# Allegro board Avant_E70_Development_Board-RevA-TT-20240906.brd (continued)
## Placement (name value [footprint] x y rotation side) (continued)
R697  2k  [R0603]  139.57 64.56 180 top
R698  732  [R0603]  139.57 63.29 180 top
R702  10K  [R0402]  137.54 73.45 270 bottom
R703  10K-DNI  [R0402]  137.92 71.29 90 bottom
R704  0-DNI  [R0402]  136.4 73.45 90 bottom
R705  10K  [R0402]  138.56 73.45 270 top
R706  10K-DNI  [R0402]  140.84 73.45 270 top
R707  10K-DNI  [R0402]  141.86 73.45 270 top
R708  10K-DNI  [R0603]  139.57 73.45 0 bottom
R709  240-DNI  [R0402]  80.77 71.17 90 bottom
R710  240-DNI  [R0402]  88.26 61.77 0 bottom
R711  240-DNI  [R0402]  62.48 66.72 270 bottom
R712  240-DNI  [R0402]  62.48 72.69 90 bottom
R713  240-DNI  [R0402]  62.48 68.88 90 bottom
R714  0.01-DNI  [R0603]  80.77 91.36 90 bottom
R715  0-DNI  [R0402]  101.98 102.79 0 bottom
R716  0-DNI  [R0402]  154.31 93.14 270 top
RDAT  VTTVREF  [TP_50]  156.24 84.95 0 top
SB_3V30  T POINT R  [TP]  132.46 49.96 0 top
ST  VTTVREF  [TP_50]  72.9 58.34 0 top
SW1  -  [430182043816]  50.04 131.62 90 top
SW2  -  [430182043816]  42.93 131.62 90 top
SW3  TDA DIP-8  [TDA08H0SB1]  55.76 46.53 270 top
SW4  -  [430182043816]  57.02 131.62 90 top
SW5  -  [430182043816]  64.01 131.62 90 top
SW7  SW-Wurth_452403012014  [452403012014]  37.72 109.9 270 top
SW8  -  [430182043816]  137.16 57.32 180 top
TP25  TestPoint_SMT  [TPC32]  154.05 12.87 0 top
TP26  TestPoint_SMT  [TPC32]  154.05 19.73 0 top
TP_AF15  T POINT R  [TP]  13.12 36.18 180 top
TP_AF16  T POINT R  [TP]  13.12 33.64 180 top
TP_AG14  T POINT R  [TP]  8.04 31.1 180 top
TP_AG15  T POINT R  [TP]  15.66 36.18 180 top
TP_AH14  T POINT R  [TP]  10.58 31.1 180 top
TP_AH15  T POINT R  [TP]  15.66 33.64 180 top
TP_AJ16  T POINT R  [TP]  2.96 31.1 180 top
TP_AK12  T POINT R  [TP]  5.5 36.18 180 top
TP_AK13  T POINT R  [TP]  5.5 33.64 180 top
TP_AK14  T POINT R  [TP]  15.66 31.1 180 top
TP_AK15  T POINT R  [TP]  13.12 31.1 180 top
TP_AK16  T POINT R  [TP]  5.5 31.1 180 top
TP_AL13  T POINT R  [TP]  8.04 36.18 180 top
TP_AM13  T POINT R  [TP]  8.04 33.64 180 top
TP_AN12  T POINT R  [TP]  8.04 38.72 180 top
TP_AN13  T POINT R  [TP]  13.12 38.72 180 top
TP_AP10  T POINT R  [TP]  2.96 38.72 180 top
TP_AP11  T POINT R  [TP]  5.5 38.72 180 top
TP_AP12  T POINT R  [TP]  10.58 38.72 180 top
TP_AP13  T POINT R  [TP]  15.66 38.72 180 top
TP_FMC2_VREFB  TestPoint  [TP50]  42.04 14.78 0 top
TP_M2C_B_1_1  TestPoint  [TP50]  5.5 42.21 0 top
TP_M2C_B_1_2  TestPoint  [TP50]  2.96 42.21 0 top
TP_M2C_B_2_1  TestPoint  [TP50]  116.84 7.16 0 top
TP_M2C_B_2_2  TestPoint  [TP50]  116.84 9.7 0 top
TP_R7  T POINT R  [TP]  30.86 110.92 0 top
U1  FT2232HL  [TQFP64_0P5_12P2X12P2_H1P6]  24.31 131.64 0 top
U2  93LC56C-I/SN  [SO8_50_244]  23.97 131.31 270 bottom
U3  LAV-AT-E70-LFG1156  [LAV-AT-500-L_1156]  80.9 79.93 0 top
U4  W25Q512JVEIM  [8-WSON]  53.47 122.35 0 top
U5  MT53E512M32D1ZW-046 WT:B  [BGA_SDRAM_200]  114.55 80.44 90 top
U6  BD9D321EFJ  [HTSOP_8_BD9D321]  40.67 48.26 180 top
U17  AP62201WU-7  [TSOT26_AP62201WU-7]  148.93 134.97 0 top
U32  BD9D321EFJ  [HTSOP_8_BD9D321]  32.41 24.66 270 top
U34  AP62201WU-7  [TSOT26_AP62201WU-7]  134.94 83 0 top
U35  AP62201WU-7  [TSOT26_AP62201WU-7]  148.93 105.76 0 top
U36  AP62201WU-7  [TSOT26_AP62201WU-7]  148.49 92.55 0 top
U37  AP62201WU-7  [TSOT26_AP62201WU-7]  134.27 96.08 0 top
U38  AP62201WU-7  [TSOT26_AP62201WU-7]  134.27 124.81 0 top
U39  AP62201WU-7  [TSOT26_AP62201WU-7]  134.27 110.33 0 top
U40  AP62201WU-7  [TSOT26_AP62201WU-7]  148.93 120.49 0 top
U41  AP62201WU-7  [TSOT26_AP62201WU-7]  148.59 81.2 0 top
U43  RT7298AHGQW  [14-WQFN]  126.9 41.68 180 top
U44  NCP133  [XFDFN6]  102.49 106.55 0 top
U45  -  [LPTM21L-CAG100]  156.84 70.66 0 top
U46  PI4ULS3V204ZBEX  [TQFN-14]  109.85 36.75 90 bottom
U107  AP62201WU-7  [TSOT26_AP62201WU-7]  138.33 45.13 0 top
U107_EN  T POINT R  [TP]  142.38 47.09 0 top
U108  MPF52002GRE-0012-Z  [QFN24N4X4P0_5]  144.78 9.95 270 top
U109  ESD1L001W1T2G  [SC-88]  150.37 16.3 270 bottom
U110  MPQ4372GVTE-1001-AEC1-Z  [QFN-23]  123.19 23.67 90 top
U111  MPQ4372GVTE-1001-AEC1-Z  [QFN-23]  145.54 23.67 270 top
U114  TPS564242DRLR  [SOT-563-6]  27.43 37.51 270 top
U115  TPS564242DRLR  [SOT-563-6]  42.55 37.51 270 top
U116  RP115H181D-T1-FE  [SOT89-5]  96.77 125.4 180 top
U118  MP2013AGG  [QFN6-MP2013]  156.97 29.26 180 top
U119  MT53E512M32D1ZW-046 WT:B  [BGA_SDRAM_200]  114.55 66.72 90 top
U120  MPM3695GPJ-20-0022-T  [ECLGA-29-5X6X4R4]  139.06 68.5 270 top
UNK0V9  T POINT R  [TP]  5.5 20.94 180 top
UNK0V82  T POINT R  [TP]  8.04 23.48 180 top
UNK0V82_EN  T POINT R  [TP]  149.99 73.83 0 top
UNK1V  T POINT R  [TP]  8.04 26.02 180 top
UNK1V1  T POINT R  [TP]  10.58 20.94 180 top
UNK1V2  T POINT R  [TP]  15.66 20.94 180 top
UNK1V5  T POINT R  [TP]  13.12 26.02 180 top
UNK1V8  T POINT R  [TP]  15.66 23.48 180 top
UNK1V35  T POINT R  [TP]  13.12 20.94 180 top
UNK1V80_EN  T POINT R  [TP]  161.89 84.66 0 top
UNK2V5  T POINT R  [TP]  2.96 20.94 180 top
UNK3V3  T POINT R  [TP]  10.58 23.48 180 top
UNK5V  T POINT R  [TP]  13.12 23.48 180 top
UNK6T  VTTVREF  [TP_50]  72.9 55.8 0 top
UNK10T  VTTVREF  [TP_50]  72.9 53.26 0 top
UNK12V  T POINT R  [TP]  8.04 20.94 180 top
VCC_3V30_EN  T POINT R  [TP]  158.01 63.39 0 top
VCCAPLL4  TestPoint_SMT  [TPC32]  118.75 108 180 top
VCCAPLL7  TestPoint_SMT  [TPC32]  118.75 103.93 180 top
VCCAPLL10  TestPoint_SMT  [TPC32]  107.45 52.93 180 top
VCCAPLLW  TestPoint_SMT  [TPC32]  100.52 96.5 180 top
VCCAUX  TestPoint_SMT  [TPC32]  100.58 113.33 270 top
VCCIO0  TestPoint_SMT  [TPC32]  46.64 105.18 90 top
VCCIO1  TestPoint_SMT  [TPC32]  92.2 103.25 0 top
VCCIO2  TestPoint_SMT  [TPC32]  57.4 81.33 0 top
VCCIO3  TestPoint_SMT  [TPC32]  69.04 114.57 0 top
VCCIO4  TestPoint_SMT  [TPC32]  76.54 114.55 0 top
VCCIO5  TestPoint_SMT  [TPC32]  86.84 114.51 0 top
VCCIO6  TestPoint_SMT  [TPC32]  111 112.95 0 top
VCCIO7  TestPoint_SMT  [TPC32]  104.68 116.69 0 top
VCCIO8  TestPoint_SMT  [TPC32]  113.44 116.69 0 top
VCCIO9  TestPoint_SMT  [TPC32]  92.84 114.85 0 top
VCCIO10  TestPoint_SMT  [TPC32]  94.49 113.2 0 top
VCCIO11  TestPoint_SMT  [TPC32]  92.84 113.2 270 top
VCCIO12  TestPoint_SMT  [TPC32]  81.49 100.24 0 top
VCCIO13  TestPoint_SMT  [TPC32]  65.02 113.58 180 top
VCCIO14  TestPoint_SMT  [TPC32]  66.34 104.63 0 top
VCCORE  TestPoint_SMT  [TPC32]  109.47 89.84 180 top
VFMC1_3V30  VTTVREF  [TP_50]  32.7 57.26 90 top
VFMC1_ADJ  TestPoint_SMT  [TPC32]  26.67 34.84 270 top
VFMC2_3V30  VTTVREF  [TP_50]  22.61 17.7 180 top
VFMC2_ADJ  TestPoint_SMT  [TPC32]  41.78 34.84 270 top
WDAT  VTTVREF  [TP_50]  149.99 68.88 0 top
WRCLK  VTTVREF  [TP_50]  159.13 87.6 0 top
X1  7M-12.000MAAJ-T  [XTAL_4P_7M]  16.13 140 180 top
X3  ASDMB-125.000MHZ-XY-T  [X4-2520]  60.2 93.77 270 top
Y1  100 MHz  [SMD6_AX3HAF1]  101.94 90.53 180 top

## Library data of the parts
AP14 DONE INIT PB1-PB3 PROGRAMN PS_EN TP25 TP26 TP_FMC2_VREFB TP_M2C_B_1_1 TP_M2C_B_1_2 TP_M2C_B_2_1 TP_M2C_B_2_2 VCCAPLL4 VCCAPLL7 VCCAPLL10 VCCAPLLW VCCAUX VCCIO0-VCCIO14 VCCORE VFMC1_ADJ VFMC2_ADJ = T POINT R
ASC_CLK P_DONE P_INITN P_JTAGENB P_PROGN PTM_SCL PTM_SDA RDAT ST UNK6T UNK10T VFMC1_3V30 VFMC2_3V30 WDAT WRCLK = TP_SMD
C1-C5 C7 C8 C10-C13 C15-C18 C20-C22 C24-C27 C29-C32 C34 C38-C40 C42-C44 C46 C48 C54 C56-C58 C60 C61 C65 C66 C69 C94 C99 C100 C526 C527 C529-C533 C535-C542 C544-C546 C548 C561 C563 C564 C579 C580 C584 C587-C590 C592-C594 C596-C600 C625 C629 C721-C729 C1177-C1180 C1185-C1189 C1191 C1192 C1198 C1199 C1202 C1203 C1214 C1215 C1219 C1220 C1258 C1259 C1666 C1667 = 0u1_0402
C6 C9 = 4u7_0603
C14 C19 C33 C37 C41 C45 C47 C49-C53 C55 C59 C62-C64 C97 C98 C101 C103 C104 C207 C208 C528 C534 C543 C547 C556-C560 C562 C565 C586 C591 C595 C614-C619 C622-C624 C626 C628 C630 C1190 C1216-C1218 C1264-C1269 C1645 C1646 C1648-C1652 C1656-C1663 = 10uF_0603
C23 C138-C140 C163 C168 C169 C402 C403 C405 C620 C621 = CAP NP
C36 C396 C397 C466 C469 C471 C474 C483 C485 C488 C510 C512 C525 C631 C1221 C1223 C1225 C1227 C1255 C1257 = C-0402_10U_6.3V_X5R_TDK
C113 = CAP POL
C142-C152 C164-C167 C171-C174 C176-C178 C289-C292 C398-C401 C404 = CAP_1
C175 = CAP_SMT_0805
C287 C288 C293 C717 = C-0402_10nF_6.3V_X5R_MURATA
C385 C632 C634 C638 C645 C649 C653 C657 C658 C662 C674 C1181 = C_0.1uF_50V_CER_0402
C386 C387 C635 C636 C639 C640 C642 C643 C646 C647 C650 C651 C654 C655 C659 C660 C663 C664 C675 C676 C1183 C1184 = C-0603_22uF_10V_X5R_Samsung
C388 C641 C644 C648 C652 C656 C661 C665 C718 C719 = C_10uf_CER_25V_0603
C465 C467 C468 C470 C472 C473 C475-C482 C484 C486 C487 C489-C509 C511 C1222 C1224 C1226 C1228-C1254 C1256 C1665 = C-0201_0.1uF_100V_X5R_MURATA
C612 C613 = C-0402_22uF_X5R_6V3_Kyocera
C637 C1182 = C-0603_10uF_16V_X5R_TaiyoYuden
C672 = C-0402_180P
C673 = C-0402_8n2F_25V_X7R_MURATA
C677 = C-0402_10nF_16V_X7R_YAGEO
C713 C714 C1193-C1196 C1204-C1211 C1260 C1261 = C-0805_22uF_25V_X5R_Yageo
C720 C732 C733 = C-0402_0.1uF_10V_X5R_MURATA
C734 = C-0402_0.1uF_6.3V_X5R_MURATA_NP
C1647 C1653-C1655 C1668 = CAP_Electrolytic_SMD_OSCON_E7
D1 D5-D13 = LED-SMT1206_GREEN_3
D3 = ESDR0502
D4 = LED-SMT1206_RED_2
D22-D29 = D- RED_LED_0
D52 D77 = TMP_0
D60 = 7SEG_LDT-N2804RI _12-DIP
D61-D70 D73-D75 D78 = LED_GREEN_0
F1_3V3 F1_3V3AUX F1_ADJ F2_3V3 F2_3V3AUX F2_ADJ GND6-GND15 PLL0V82_EN SB_3V30 TP_AF15 TP_AF16 TP_AG14 TP_AG15 TP_AH14 TP_AH15 TP_AJ16 TP_AK12-TP_AK16 TP_AL13 TP_AM13 TP_AN12 TP_AN13 TP_AP10-TP_AP13 TP_R7 U107_EN UNK0V9 UNK0V82 UNK0V82_EN UNK1V UNK1V1 UNK1V2 UNK1V5 UNK1V8 UNK1V35 UNK1V80_EN UNK2V5 UNK3V3 UNK5V UNK12V VCC_3V30_EN = T POINT R_0
FB1-FB3 FB6 = INDUCTOR_1
FB4 FB24 = FB_0806_120R_TaiyoYuden
FB16 L1 L4 L5 L8 L10 L13-L18 L20 L23 = INDUCTOR_0
FB22 FB25-FB27 = FB_0402_600R_Murata
FB28 FB29 = FB _220E_0603
GND1-GND5 = TP_S_40_63
J1 J39 = header1x8_100
J2 = USB_MINI_B_1
J3 J10 J53 J83 = Header_2x7
J6 J7 = SKT2x6_PPPC062LFBN-RC
J8 = CON3
J11 = HEADER 2
J23 J57 = Header_2x1
J25 = USB_TYPEC_SMT
J31-J33 J81 = HEADER 1
J48 J54 = ASP-134486-01_0
J50 = J_JACK_2.10mm
J58-J60 J63-J73 J76-J80 = J-Header_2x1
J84 = 1201M2S3AQE2
JP1-JP6 JP12 JP13 JP15 JP17 = JUMPER_0
JP26 = Receptacle 20X2
JP31-JP36 JP38 JP40 JP42 JP47-JP51 JP58-JP62 JP69-JP78 = J-2 Pin Jumper
JP64 JP65 JP83-JP86 JP88 JP89 = 3-PINS 0.1" SINGLE LINE PIN
L3 L6 = FB0603_0
L19 = L-1uH_BOURNS
L21 L24 L25 = L-4u7H_4.1A_TaiyoYuden
Q1 = 2N2222_0
Q2-Q4 Q7-Q24 Q27-Q34 = TRANS NPN 45V 0_0.8A SOT-23
Q26 = 2N3796_0
R1 R15 R19 R126 R127 R289 R549-R552 R554 R680 R681 = 10k_0402
R2-R5 R11 R21 R27 R30-R37 R42 R47 R48 R76-R79 R92 R185 R192 R215 R216 R308 R309 R317 R603-R623 R638-R643 R649-R651 R659-R676 = 5k1_0402
R6-R10 R52 R103-R108 R189 R652-R656 R695 R696 R704 R709-R713 R715 R716 = 0R_0603
R12-R14 R23 R29 R50 R51 R80 R81 R179 R180 R398 R686 = RES_10K_1W16_0402_5P
R16 R17 R109 = RESISTOR
R20 R22 R26 R43-R46 R55 R83-R87 R90 R91 R95 R217 R249-R252 R292 R293 R307 R310 R314-R316 R321-R328 R345 R399 R401 R402 R406 R408 R536 R542 R543 R596-R598 R601 R602 R624 R625 R628 R629 R644-R647 R657 = R
R24 R25 R56-R63 = 1k_0402
R28 = RES_0
R38 R572 = R0402_10K_5%_VISHAY
R39-R41 = R0402_10K_NP
R54 R693 R694 R697 R698 R702 R703 R705-R707 = RES_1K_1W16_0402_5P
R82 R298 = R0402_0.01R_1%_YAGEO
R96 R305 = R0402_1K_1%_Yageo
R100 R306 = R0402_301R_1%_Yageo
R110 = 1R_0.25W_0603
R137 R139 R140 R142 R143 R147 R353 R370 R374 R378 R387 R391 R395 R714 = R0603_0.01_1%_Yageo
R154 = R0603_0R1_1%_VishayDale
R169 R339 R341 R343 R411 R417 R427 R433 R439 R444 R447 R453 R475 R521 R523 R524 R526 R528 R529 R532 R533 R546 R567 = R_330R_0603
R229 R416 R426 R432 R438 R443 R446 R452 R474 R520 R522 R525 R527 R530 R531 R534 R535 R547 R683 R684 R687-R692 = R_10K_0603
R231 = R0603_2K61_1%_Yageo
R232 R415 R421 R424 R430 R436 R442 R451 R457 R569 R682 R708 = R0603_10K_1%_Yageo
R233 R412 R418 R428 R434 R441 R448 R454 = R_42.2K_0402
R234 R413 R419 R429 R435 R440 R449 R455 = R_12.7K_0402
R245 = R0402_0R_DNI_PANASONIC
R267 R539-R541 = R0603_1R_1%_Panasonic_1/4W
R287 R288 = R0603_19K1_1%_Yageo
R290 R291 R294 R633 R685 = R0402_240_5%_YAGEO
R331-R338 = R_53.6R_0402
R340 R342 R344 = R_4.7K_0603
R414 R566 = R0603_31K6_1%_Yageo
R420 = R0603_3K83_1%_Yageo
R425 = R0603_12K7_1%_Yageo
R431 = R0603_5K11_1%_Yageo
R437 = R0603_21K5_1%_Yageo
R445 = R0603_8K87_1%_Yageo
R450 = R0603_1K33_1%_Yageo
R456 = R0603_6K98_1%_Yageo
R463 = R0603_4K3_1%_Yageo
R464 = R0603_176K_0.5%_Yageo
R465 = R0603_24K_1%_Yageo
R466 R467 = R0603_100K_1%_Yageo
R490 R491 = R0201_49R9_1%_YAGEO
R492 R493 = R0402_0R_NP_5%_PANASONIC
R510 = R0402_1K_5%_VISHAY
R519 = R0402_3K6_5%_YAGEO
R537 R538 R548 R575-R577 R583 R584 = R0402_0R_5%_PANASONIC
R544 = R0603_2K_1%_Yageo
R545 = R0603_80K6_1%_Yageo
R556 = R0603_10K_5%_Yageo
R561 R562 = R0603_5K9_1%_Yageo
R563 R564 = R0603_3K4_1%_Yageo
R565 = R0603_5K62_1%_Yageo
R568 = R0402_3K_1%_Yageo
R578 = R0603_33R_5%_Yageo
R579 = R0402_330R
R582 R636 = R0402_100_1%_YAGEO
R585 = RES_100K_1W16_0402_5P
R588 R589 = R0603_NP
R599 R600 R648 = R: signal model: R_R0402_10_10
R658 = RES_2: alternate symbols: (RESC100X50X40RND)
SW1 SW2 SW4 SW5 SW8 = EVQP0_0
SW3 = SW DIP-8
SW7 = SW-Wurth_452403012014
U1 = FT2232HL
U2 = 93LC56_SO8_0
U3 = LAV-AT-E70-LFG1156_6
U4 = U-W25Q512JVEIM_512Mb_Flash_0
U5 U119 = IC_MT53E128M32D2DS-053_200FBGA
U6 U32 = BD9D321EFJ
U17 U34-U41 U107 = U-AP62201WU-7
U43 = U-RT7298AHGQW_Richtek
U44 = U-NCP133_LDOR_1
U45 = LPTM21L-CAG100
U46 = U-PI4ULS3V204ZBEX
U108 = MPF52002
U109 = ESD1L001
U110 U111 = MPQ4371
U114 U115 = TPS564242DRLR
U116 = RP111HXX1D
U118 = MP2013A
U120 = MPM3695-20_0
X1 = crystal-3p2x2p5
X3 = ASDMB
Y1 = Y_100 Mhz_HCSL

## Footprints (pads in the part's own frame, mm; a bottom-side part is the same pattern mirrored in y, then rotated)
0P1_2-PIN_TH
  rect 1.524x1.524 hole 1.016: 1(-1.27,0)
  round 1.524 hole 1.016: 2(1.27,0)
8-WSON
  rect 1.058x0.734 smd: 1(-3.775,1.905) 2(-3.775,0.635) 3(-3.775,-0.635) 4(-3.775,-1.905) 5(3.775,-1.905) 6(3.775,-0.635) 7(3.775,0.635) 8(3.775,1.905)
  rect 3.45x4.35 smd: 9(0,0)
8MMX8MM
  rect 1.8x7.5 smd: 1(-2.8,0) 2(2.8,0)
14-WQFN
  rect 0.3x0.704 smd: 1(-0.75,1.575) 7(-0.75,-1.575) 8(0.75,-1.575) 14(0.75,1.575)
  rect 0.704x0.3 smd: 2(-1.575,1) 3(-1.575,0.5) 4(-1.575,0) 5(-1.575,-0.5) 6(-1.575,-1) 9(1.575,-1) 10(1.575,-0.5) 11(1.575,0) 12(1.575,0.5) 13(1.575,1)
  custom 0.525x0.525 smd: 15(0,0)
0402
  rect 0.56x0.63 smd: 1(-0.485,0) 2(0.485,0)
0603
  rect 0.813x0.762 smd: 1(-0.762,0) 2(0.762,0)
0806
  rect 1.4x2 smd: 1(-1.2,0) 2(1.2,0)
1201M2S3AQE2
  round 2.85 hole 1.85: (-6.605,-16.51) (6.605,-16.51) 1(4.7,-3.81) 2(0,-3.81) 3(-4.7,-3.81) 4(4.7,0) 5(0,0) 6(-4.7,0)
7360-20
  rect 2.48x4.52 smd: 1(-2.99,0) 2(2.99,0)
22284024
  rect 1.524x1.524 hole 1.016: 1(-1.27,0)
  round 1.524 hole 1.016: 2(1.27,0)
430182043816
  rect 1.55x1.3 smd: 1(-3.975,2.25) 2(-3.975,-2.25) 3(3.975,2.25) 4(3.975,-2.25)
452403012014
  rect 1.2x1.5 smd: 1(-2.5,3.25) 2(0,3.25) 3(2.5,3.25) 4(-2.5,-3.25) 5(0,-3.25) 6(2.5,-3.25)
694106301002
  rect 1.308x3.508 hole 0.8x3: 1(13.6,0) 2(7.8,0)
  rect 3.508x1.308 hole 3x0.8: 3(10.6,-4.8)
APT1608
  rect 0.8x0.8 smd: A(0,0.826) K(0,-0.826)
ASP-134486-01
  round 6 hole 2.7: (-31.496,2.007) (31.496,2.007)
  round 1.27 hole 1.27 unplated: (-27.178,0) (27.178,-3.048)
  round 0.635 smd: A1(24.765,-5.715) A2(23.495,-5.715) A3(22.225,-5.715) A4(20.955,-5.715) A5(19.685,-5.715) A6(18.415,-5.715) A7(17.145,-5.715) A8(15.875,-5.715) A9(14.605,-5.715) A10(13.335,-5.715) A11(12.065,-5.715) A12(10.795,-5.715) A13(9.525,-5.715) A14(8.255,-5.715) A15(6.985,-5.715) A16(5.715,-5.715) A17(4.445,-5.715) A18(3.175,-5.715) A19(1.905,-5.715) A20(0.635,-5.715) A21(-0.635,-5.715) A22(-1.905,-5.715) A23(-3.175,-5.715) A24(-4.445,-5.715) A25(-5.715,-5.715) A26(-6.985,-5.715) A27(-8.255,-5.715) A28(-9.525,-5.715) A29(-10.795,-5.715) A30(-12.065,-5.715) A31(-13.335,-5.715) A32(-14.605,-5.715) A33(-15.875,-5.715) A34(-17.145,-5.715) A35(-18.415,-5.715) A36(-19.685,-5.715) A37(-20.955,-5.715) A38(-22.225,-5.715) A39(-23.495,-5.715) A40(-24.765,-5.715) B1(24.765,-4.445) B2(23.495,-4.445) B3(22.225,-4.445) B4(20.955,-4.445) B5(19.685,-4.445) B6(18.415,-4.445) B7(17.145,-4.445) B8(15.875,-4.445) B9(14.605,-4.445) B10(13.335,-4.445) B11(12.065,-4.445) B12(10.795,-4.445) B13(9.525,-4.445) B14(8.255,-4.445) B15(6.985,-4.445) B16(5.715,-4.445) B17(4.445,-4.445) B18(3.175,-4.445) B19(1.905,-4.445) B20(0.635,-4.445) B21(-0.635,-4.445) B22(-1.905,-4.445) B23(-3.175,-4.445) B24(-4.445,-4.445) B25(-5.715,-4.445) B26(-6.985,-4.445) B27(-8.255,-4.445) B28(-9.525,-4.445) B29(-10.795,-4.445) B30(-12.065,-4.445) B31(-13.335,-4.445) B32(-14.605,-4.445) B33(-15.875,-4.445) B34(-17.145,-4.445) B35(-18.415,-4.445) B36(-19.685,-4.445) B37(-20.955,-4.445) B38(-22.225,-4.445) B39(-23.495,-4.445) B40(-24.765,-4.445) C1(24.765,-3.175) C2(23.495,-3.175) C3(22.225,-3.175) C4(20.955,-3.175) C5(19.685,-3.175) C6(18.415,-3.175) C7(17.145,-3.175) C8(15.875,-3.175) C9(14.605,-3.175) C10(13.335,-3.175) C11(12.065,-3.175) C12(10.795,-3.175) C13(9.525,-3.175) C14(8.255,-3.175) C15(6.985,-3.175) C16(5.715,-3.175) C17(4.445,-3.175) C18(3.175,-3.175) C19(1.905,-3.175) C20(0.635,-3.175) C21(-0.635,-3.175) C22(-1.905,-3.175) C23(-3.175,-3.175) C24(-4.445,-3.175) C25(-5.715,-3.175) C26(-6.985,-3.175) C27(-8.255,-3.175) C28(-9.525,-3.175) C29(-10.795,-3.175) C30(-12.065,-3.175) C31(-13.335,-3.175) C32(-14.605,-3.175) C33(-15.875,-3.175) C34(-17.145,-3.175) C35(-18.415,-3.175) C36(-19.685,-3.175) C37(-20.955,-3.175) C38(-22.225,-3.175) C39(-23.495,-3.175) C40(-24.765,-3.175) D1(24.765,-1.905) D2(23.495,-1.905) D3(22.225,-1.905) D4(20.955,-1.905) D5(19.685,-1.905) D6(18.415,-1.905) D7(17.145,-1.905) D8(15.875,-1.905) D9(14.605,-1.905) D10(13.335,-1.905) D11(12.065,-1.905) D12(10.795,-1.905) D13(9.525,-1.905) D14(8.255,-1.905) D15(6.985,-1.905) D16(5.715,-1.905) D17(4.445,-1.905) D18(3.175,-1.905) D19(1.905,-1.905) D20(0.635,-1.905) D21(-0.635,-1.905) D22(-1.905,-1.905) D23(-3.175,-1.905) D24(-4.445,-1.905) D25(-5.715,-1.905) D26(-6.985,-1.905) D27(-8.255,-1.905) D28(-9.525,-1.905) D29(-10.795,-1.905) D30(-12.065,-1.905) D31(-13.335,-1.905) D32(-14.605,-1.905) D33(-15.875,-1.905) D34(-17.145,-1.905) D35(-18.415,-1.905) D36(-19.685,-1.905) D37(-20.955,-1.905) D38(-22.225,-1.905) D39(-23.495,-1.905) D40(-24.765,-1.905) E1(24.765,-0.635) E2(23.495,-0.635) E3(22.225,-0.635) E4(20.955,-0.635) E5(19.685,-0.635) E6(18.415,-0.635) E7(17.145,-0.635) E8(15.875,-0.635) E9(14.605,-0.635) E10(13.335,-0.635) E11(12.065,-0.635) E12(10.795,-0.635) E13(9.525,-0.635) E14(8.255,-0.635) E15(6.985,-0.635) E16(5.715,-0.635) E17(4.445,-0.635) E18(3.175,-0.635) E19(1.905,-0.635) E20(0.635,-0.635) E21(-0.635,-0.635) E22(-1.905,-0.635) E23(-3.175,-0.635) E24(-4.445,-0.635) E25(-5.715,-0.635) E26(-6.985,-0.635) E27(-8.255,-0.635) E28(-9.525,-0.635) E29(-10.795,-0.635) E30(-12.065,-0.635) E31(-13.335,-0.635) E32(-14.605,-0.635) E33(-15.875,-0.635) E34(-17.145,-0.635) E35(-18.415,-0.635) E36(-19.685,-0.635) E37(-20.955,-0.635) E38(-22.225,-0.635) E39(-23.495,-0.635) E40(-24.765,-0.635) F1(24.765,0.635) F2(23.495,0.635) F3(22.225,0.635) F4(20.955,0.635) F5(19.685,0.635) F6(18.415,0.635) F7(17.145,0.635) F8(15.875,0.635) F9(14.605,0.635) F10(13.335,0.635) F11(12.065,0.635) F12(10.795,0.635) F13(9.525,0.635) F14(8.255,0.635) F15(6.985,0.635) F16(5.715,0.635) F17(4.445,0.635) F18(3.175,0.635) F19(1.905,0.635) F20(0.635,0.635) F21(-0.635,0.635) F22(-1.905,0.635) F23(-3.175,0.635) F24(-4.445,0.635) F25(-5.715,0.635) F26(-6.985,0.635) F27(-8.255,0.635) F28(-9.525,0.635) F29(-10.795,0.635) F30(-12.065,0.635) F31(-13.335,0.635) F32(-14.605,0.635) F33(-15.875,0.635) F34(-17.145,0.635) F35(-18.415,0.635) F36(-19.685,0.635) F37(-20.955,0.635) F38(-22.225,0.635) F39(-23.495,0.635) F40(-24.765,0.635) G1(24.765,1.905) G2(23.495,1.905) G3(22.225,1.905) G4(20.955,1.905) G5(19.685,1.905) G6(18.415,1.905) G7(17.145,1.905) G8(15.875,1.905) G9(14.605,1.905) G10(13.335,1.905) G11(12.065,1.905) G12(10.795,1.905) G13(9.525,1.905) G14(8.255,1.905) G15(6.985,1.905) G16(5.715,1.905) G17(4.445,1.905) G18(3.175,1.905) G19(1.905,1.905) G20(0.635,1.905) G21(-0.635,1.905) G22(-1.905,1.905) G23(-3.175,1.905) G24(-4.445,1.905) G25(-5.715,1.905) G26(-6.985,1.905) G27(-8.255,1.905) G28(-9.525,1.905) G29(-10.795,1.905) G30(-12.065,1.905) G31(-13.335,1.905) G32(-14.605,1.905) G33(-15.875,1.905) G34(-17.145,1.905) G35(-18.415,1.905) G36(-19.685,1.905) G37(-20.955,1.905) G38(-22.225,1.905) G39(-23.495,1.905) G40(-24.765,1.905) H1(24.765,3.175) H2(23.495,3.175) H3(22.225,3.175) H4(20.955,3.175) H5(19.685,3.175) H6(18.415,3.175) H7(17.145,3.175) H8(15.875,3.175) H9(14.605,3.175) H10(13.335,3.175) H11(12.065,3.175) H12(10.795,3.175) H13(9.525,3.175) H14(8.255,3.175) H15(6.985,3.175) H16(5.715,3.175) H17(4.445,3.175) H18(3.175,3.175) H19(1.905,3.175) H20(0.635,3.175) H21(-0.635,3.175) H22(-1.905,3.175) H23(-3.175,3.175) H24(-4.445,3.175) H25(-5.715,3.175) H26(-6.985,3.175) H27(-8.255,3.175) H28(-9.525,3.175) H29(-10.795,3.175) H30(-12.065,3.175) H31(-13.335,3.175) H32(-14.605,3.175) H33(-15.875,3.175) H34(-17.145,3.175) H35(-18.415,3.175) H36(-19.685,3.175) H37(-20.955,3.175) H38(-22.225,3.175) H39(-23.495,3.175) H40(-24.765,3.175) J1(24.765,4.445) J2(23.495,4.445) J3(22.225,4.445) J4(20.955,4.445) J5(19.685,4.445) J6(18.415,4.445) J7(17.145,4.445) J8(15.875,4.445) J9(14.605,4.445) J10(13.335,4.445) J11(12.065,4.445) J12(10.795,4.445) J13(9.525,4.445) J14(8.255,4.445) J15(6.985,4.445) J16(5.715,4.445) J17(4.445,4.445) J18(3.175,4.445) J19(1.905,4.445) J20(0.635,4.445) J21(-0.635,4.445) J22(-1.905,4.445) J23(-3.175,4.445) J24(-4.445,4.445) J25(-5.715,4.445) J26(-6.985,4.445) J27(-8.255,4.445) J28(-9.525,4.445) J29(-10.795,4.445) J30(-12.065,4.445) J31(-13.335,4.445) J32(-14.605,4.445) J33(-15.875,4.445) J34(-17.145,4.445) J35(-18.415,4.445) J36(-19.685,4.445) J37(-20.955,4.445) J38(-22.225,4.445) J39(-23.495,4.445) J40(-24.765,4.445) K1(24.765,5.715) K2(23.495,5.715) K3(22.225,5.715) K4(20.955,5.715) K5(19.685,5.715) K6(18.415,5.715) K7(17.145,5.715) K8(15.875,5.715) K9(14.605,5.715) K10(13.335,5.715) K11(12.065,5.715) K12(10.795,5.715) K13(9.525,5.715) K14(8.255,5.715) K15(6.985,5.715) K16(5.715,5.715) K17(4.445,5.715) K18(3.175,5.715) K19(1.905,5.715) K20(0.635,5.715) K21(-0.635,5.715) K22(-1.905,5.715) K23(-3.175,5.715) K24(-4.445,5.715) K25(-5.715,5.715) K26(-6.985,5.715) K27(-8.255,5.715) K28(-9.525,5.715) K29(-10.795,5.715) K30(-12.065,5.715) K31(-13.335,5.715) K32(-14.605,5.715) K33(-15.875,5.715) K34(-17.145,5.715) K35(-18.415,5.715) K36(-19.685,5.715) K37(-20.955,5.715) K38(-22.225,5.715) K39(-23.495,5.715) K40(-24.765,5.715)
BGA_SDRAM_200
  round 0.363 smd: A1(-4.4,6.825) A2(-3.6,6.825) A3(-2.8,6.825) A4(-2,6.825) A5(-1.2,6.825) A8(1.2,6.825) A9(2,6.825) A10(2.8,6.825) A11(3.6,6.825) A12(4.4,6.825) AA1(-4.4,-6.175) AA2(-3.6,-6.175) AA3(-2.8,-6.175) AA4(-2,-6.175) AA5(-1.2,-6.175) AA8(1.2,-6.175) AA9(2,-6.175) AA10(2.8,-6.175) AA11(3.6,-6.175) AA12(4.4,-6.175) AB1(-4.4,-6.825) AB2(-3.6,-6.825) AB3(-2.8,-6.825) AB4(-2,-6.825) AB5(-1.2,-6.825) AB8(1.2,-6.825) AB9(2,-6.825) AB10(2.8,-6.825) AB11(3.6,-6.825) AB12(4.4,-6.825) B1(-4.4,6.175) B2(-3.6,6.175) B3(-2.8,6.175) B4(-2,6.175) B5(-1.2,6.175) B8(1.2,6.175) B9(2,6.175) B10(2.8,6.175) B11(3.6,6.175) B12(4.4,6.175) C1(-4.4,5.525) C2(-3.6,5.525) C3(-2.8,5.525) C4(-2,5.525) C5(-1.2,5.525) C8(1.2,5.525) C9(2,5.525) C10(2.8,5.525) C11(3.6,5.525) C12(4.4,5.525) D1(-4.4,4.875) D2(-3.6,4.875) D3(-2.8,4.875) D4(-2,4.875) D5(-1.2,4.875) D8(1.2,4.875) D9(2,4.875) D10(2.8,4.875) D11(3.6,4.875) D12(4.4,4.875) E1(-4.4,4.225) E2(-3.6,4.225) E3(-2.8,4.225) E4(-2,4.225) E5(-1.2,4.225) E8(1.2,4.225) E9(2,4.225) E10(2.8,4.225) E11(3.6,4.225) E12(4.4,4.225) F1(-4.4,3.575) F2(-3.6,3.575) F3(-2.8,3.575) F4(-2,3.575) F5(-1.2,3.575) F8(1.2,3.575) F9(2,3.575) F10(2.8,3.575) F11(3.6,3.575) F12(4.4,3.575) G1(-4.4,2.925) G2(-3.6,2.925) G3(-2.8,2.925) G4(-2,2.925) G5(-1.2,2.925) G8(1.2,2.925) G9(2,2.925) G10(2.8,2.925) G11(3.6,2.925) G12(4.4,2.925) H1(-4.4,2.275) H2(-3.6,2.275) H3(-2.8,2.275) H4(-2,2.275) H5(-1.2,2.275) H8(1.2,2.275) H9(2,2.275) H10(2.8,2.275) H11(3.6,2.275) H12(4.4,2.275) J1(-4.4,1.625) J2(-3.6,1.625) J3(-2.8,1.625) J4(-2,1.625) J5(-1.2,1.625) J8(1.2,1.625) J9(2,1.625) J10(2.8,1.625) J11(3.6,1.625) J12(4.4,1.625) K1(-4.4,0.975) K2(-3.6,0.975) K3(-2.8,0.975) K4(-2,0.975) K5(-1.2,0.975) K8(1.2,0.975) K9(2,0.975) K10(2.8,0.975) K11(3.6,0.975) K12(4.4,0.975) N1(-4.4,-0.975) N2(-3.6,-0.975) N3(-2.8,-0.975) N4(-2,-0.975) N5(-1.2,-0.975) N8(1.2,-0.975) N9(2,-0.975) N10(2.8,-0.975) N11(3.6,-0.975) N12(4.4,-0.975) P1(-4.4,-1.625) P2(-3.6,-1.625) P3(-2.8,-1.625) P4(-2,-1.625) P5(-1.2,-1.625) P8(1.2,-1.625) P9(2,-1.625) P10(2.8,-1.625) P11(3.6,-1.625) P12(4.4,-1.625) R1(-4.4,-2.275) R2(-3.6,-2.275) R3(-2.8,-2.275) R4(-2,-2.275) R5(-1.2,-2.275) R8(1.2,-2.275) R9(2,-2.275) R10(2.8,-2.275) R11(3.6,-2.275) R12(4.4,-2.275) T1(-4.4,-2.925) T2(-3.6,-2.925) T3(-2.8,-2.925) T4(-2,-2.925) T5(-1.2,-2.925) T8(1.2,-2.925) T9(2,-2.925) T10(2.8,-2.925) T11(3.6,-2.925) T12(4.4,-2.925) U1(-4.4,-3.575) U2(-3.6,-3.575) U3(-2.8,-3.575) U4(-2,-3.575) U5(-1.2,-3.575) U8(1.2,-3.575) U9(2,-3.575) U10(2.8,-3.575) U11(3.6,-3.575) U12(4.4,-3.575) V1(-4.4,-4.225) V2(-3.6,-4.225) V3(-2.8,-4.225) V4(-2,-4.225) V5(-1.2,-4.225) V8(1.2,-4.225) V9(2,-4.225) V10(2.8,-4.225) V11(3.6,-4.225) V12(4.4,-4.225) W1(-4.4,-4.875) W2(-3.6,-4.875) W3(-2.8,-4.875) W4(-2,-4.875) W5(-1.2,-4.875) W8(1.2,-4.875) W9(2,-4.875) W10(2.8,-4.875) W11(3.6,-4.875) W12(4.4,-4.875) Y1(-4.4,-5.525) Y2(-3.6,-5.525) Y3(-2.8,-5.525) Y4(-2,-5.525) Y5(-1.2,-5.525) Y8(1.2,-5.525) Y9(2,-5.525) Y10(2.8,-5.525) Y11(3.6,-5.525) Y12(4.4,-5.525)
C0201
  rect 0.275x0.3 smd: 1(-0.262,0) 2(0.262,0)
C0402
  rect 0.65x0.65 smd: 1(-0.45,0) 2(0.45,0)
C0603
  rect 0.889x0.813 smd: 1(-0.762,0) 2(0.762,0)
C0805
  rect 1.016x1.27 smd: 1(-0.826,0) 2(0.826,0)
C1210
  rect 1.16x2.72 smd: 1(-1.475,0) 2(1.475,0)
DISPLAY_12P-PTH
  rect 1.136x1.136 hole 0.628: 1(-6.35,-3.81)
  round 1.136 hole 0.628: 2(-3.81,-3.81) 3(-1.27,-3.81) 4(1.27,-3.81) 5(3.81,-3.81) 6(6.35,-3.81) 7(6.35,3.81) 8(3.81,3.81) 9(1.27,3.81) 10(-1.27,3.81) 11(-3.81,3.81) 12(-6.35,3.81)
ECLGA-29-5X6X4R4
  rect 0.7x0.525 smd: 1(-2.05,2.638) 11(-2.05,-2.638) 15(2.05,-2.638) 25(2.05,2.638)
  rect 0.5x0.25 smd: 2(-2.15,2) 3(-2.15,1.5) 4(-2.15,1) 5(-2.15,0.5) 6(-2.15,0) 7(-2.15,-0.5) 8(-2.15,-1) 9(-2.15,-1.5) 10(-2.15,-2) 16(2.15,-2) 17(2.15,-1.5) 18(2.15,-1) 19(2.15,-0.5) 20(2.15,0) 21(2.15,0.5) 22(2.15,1) 23(2.15,1.5) 24(2.15,2)
  rect 0.35x2.4 smd: 12(-1.15,-1.7) 13(0,-1.7) 14(1.15,-1.7) 26(1.15,1.7) 27(0.55,1.7) 28(-0.55,1.7) 29(-1.15,1.7)
FB0402
  rect 0.55x0.55 smd: 1(-0.5,0) 2(0.5,0)
FB0603
  rect 0.65x1 smd: 1(-0.675,0) 2(0.675,0)
HDR1X3
  rect 1.524x1.524 hole 1.016: 1(-2.54,0)
  round 1.524 hole 1.016: 2(0,0) 3(2.54,0)
HDR254-2X20_SOCKET
  rect 1.524x1.524 hole 1.016: 1(-24.13,1.27)
  round 1.524 hole 1.016: 2(-24.13,-1.27) 3(-21.59,1.27) 4(-21.59,-1.27) 5(-19.05,1.27) 6(-19.05,-1.27) 7(-16.51,1.27) 8(-16.51,-1.27) 9(-13.97,1.27) 10(-13.97,-1.27) 11(-11.43,1.27) 12(-11.43,-1.27) 13(-8.89,1.27) 14(-8.89,-1.27) 15(-6.35,1.27) 16(-6.35,-1.27) 17(-3.81,1.27) 18(-3.81,-1.27) 19(-1.27,1.27) 20(-1.27,-1.27) 21(1.27,1.27) 22(1.27,-1.27) 23(3.81,1.27) 24(3.81,-1.27) 25(6.35,1.27) 26(6.35,-1.27) 27(8.89,1.27) 28(8.89,-1.27) 29(11.43,1.27) 30(11.43,-1.27) 31(13.97,1.27) 32(13.97,-1.27) 33(16.51,1.27) 34(16.51,-1.27) 35(19.05,1.27) 36(19.05,-1.27) 37(21.59,1.27) 38(21.59,-1.27) 39(24.13,1.27) 40(24.13,-1.27)
HDR254M-1X3
  rect 1.524x1.524 hole 1.016: 1(-2.54,0)
  round 1.524 hole 1.016: 2(0,0) 3(2.54,0)
HDR_AMP_87220_8_1X8_100
  rect 1.524x1.524 hole 1.016: 1(0,0)
  round 1.524 hole 1.016: 2(2.54,0) 3(5.08,0) 4(7.62,0) 5(10.16,0) 6(12.7,0) 7(15.24,0) 8(17.78,0)
HEADER_1X2
  rect 1.524x1.524 hole 1.016: 1(-1.27,0)
  round 1.524 hole 1.016: 2(1.27,0)
HEADER_2X1
  rect 1.524x1.524 hole 1.016: 1(-1.27,0)
  round 1.524 hole 1.016: 2(1.27,0)
HEADER_2X1_100MIL
  rect 1.524x1.524 hole 1.016: 1(-1.27,0)
  round 1.524 hole 1.016: 2(1.27,0)
HEADER_2X7
  rect 1.524x1.524 hole 1.016: 1(-7.62,-1.27)
  round 1.524 hole 1.016: 2(-7.62,1.27) 3(-5.08,-1.27) 4(-5.08,1.27) 5(-2.54,-1.27) 6(-2.54,1.27) 7(0,-1.27) 8(0,1.27) 9(2.54,-1.27) 10(2.54,1.27) 11(5.08,-1.27) 12(5.08,1.27) 13(7.62,-1.27) 14(7.62,1.27)
HTSOP_8_BD9D321
  rect 1.2x0.7 smd: 1(-2.9,1.905) 2(-2.9,0.635) 3(-2.9,-0.635) 4(-2.9,-1.905) 5(2.9,-1.905) 6(2.9,-0.635) 7(2.9,0.635) 8(2.9,1.905)
  rect 2.4x3.2 smd: 9(0,0)
L6R6X6R4-4R8
  rect 1.55x5.6 smd: 1(-2.025,0) 2(2.025,0)
LAV-AT-500-L_1156
  round 0.56 smd: A1(-16.5,16.5) A2(-15.5,16.5) A3(-14.5,16.5) A4(-13.5,16.5) A5(-12.5,16.5) A6(-11.5,16.5) A7(-10.5,16.5) A8(-9.5,16.5) A9(-8.5,16.5) A10(-7.5,16.5) A11(-6.5,16.5) A12(-5.5,16.5) A13(-4.5,16.5) A14(-3.5,16.5) A15(-2.5,16.5) A16(-1.5,16.5) A17(-0.5,16.5) A18(0.5,16.5) A19(1.5,16.5) A20(2.5,16.5) A21(3.5,16.5) A22(4.5,16.5) A23(5.5,16.5) A24(6.5,16.5) A25(7.5,16.5) A26(8.5,16.5) A27(9.5,16.5) A28(10.5,16.5) A29(11.5,16.5) A30(12.5,16.5) A31(13.5,16.5) A32(14.5,16.5) A33(15.5,16.5) A34(16.5,16.5) AA1(-16.5,-3.5) AA2(-15.5,-3.5) AA3(-14.5,-3.5) AA4(-13.5,-3.5) AA5(-12.5,-3.5) AA6(-11.5,-3.5) AA7(-10.5,-3.5) AA8(-9.5,-3.5) AA9(-8.5,-3.5) AA10(-7.5,-3.5) AA11(-6.5,-3.5) AA12(-5.5,-3.5) AA13(-4.5,-3.5) AA14(-3.5,-3.5) AA15(-2.5,-3.5) AA16(-1.5,-3.5) AA17(-0.5,-3.5) AA18(0.5,-3.5) AA19(1.5,-3.5) AA20(2.5,-3.5) AA21(3.5,-3.5) AA22(4.5,-3.5) AA23(5.5,-3.5) AA24(6.5,-3.5) AA25(7.5,-3.5) AA26(8.5,-3.5) AA27(9.5,-3.5) AA28(10.5,-3.5) AA29(11.5,-3.5) AA30(12.5,-3.5) AA31(13.5,-3.5) AA32(14.5,-3.5) AA33(15.5,-3.5) AA34(16.5,-3.5) AB1(-16.5,-4.5) AB2(-15.5,-4.5) AB3(-14.5,-4.5) AB4(-13.5,-4.5) AB5(-12.5,-4.5) AB6(-11.5,-4.5) AB7(-10.5,-4.5) AB8(-9.5,-4.5) AB9(-8.5,-4.5) AB10(-7.5,-4.5) AB11(-6.5,-4.5) AB12(-5.5,-4.5) AB13(-4.5,-4.5) AB14(-3.5,-4.5) AB15(-2.5,-4.5) AB16(-1.5,-4.5) AB17(-0.5,-4.5) AB18(0.5,-4.5) AB19(1.5,-4.5) AB20(2.5,-4.5) AB21(3.5,-4.5) AB22(4.5,-4.5) AB23(5.5,-4.5) AB24(6.5,-4.5) AB25(7.5,-4.5) AB26(8.5,-4.5) AB27(9.5,-4.5) AB28(10.5,-4.5) AB29(11.5,-4.5) AB30(12.5,-4.5) AB31(13.5,-4.5) AB32(14.5,-4.5) AB33(15.5,-4.5) AB34(16.5,-4.5) AC1(-16.5,-5.5) AC2(-15.5,-5.5) AC3(-14.5,-5.5) AC4(-13.5,-5.5) AC5(-12.5,-5.5) AC6(-11.5,-5.5) AC7(-10.5,-5.5) AC8(-9.5,-5.5) AC9(-8.5,-5.5) AC10(-7.5,-5.5) AC11(-6.5,-5.5) AC12(-5.5,-5.5) AC13(-4.5,-5.5) AC14(-3.5,-5.5) AC15(-2.5,-5.5) AC16(-1.5,-5.5) AC17(-0.5,-5.5) AC18(0.5,-5.5) AC19(1.5,-5.5) AC20(2.5,-5.5) AC21(3.5,-5.5) AC22(4.5,-5.5) AC23(5.5,-5.5) AC24(6.5,-5.5) AC25(7.5,-5.5) AC26(8.5,-5.5) AC27(9.5,-5.5) AC28(10.5,-5.5) AC29(11.5,-5.5) AC30(12.5,-5.5) AC31(13.5,-5.5) AC32(14.5,-5.5) AC33(15.5,-5.5) AC34(16.5,-5.5) AD1(-16.5,-6.5) AD2(-15.5,-6.5) AD3(-14.5,-6.5) AD4(-13.5,-6.5) AD5(-12.5,-6.5) AD6(-11.5,-6.5) AD7(-10.5,-6.5) AD8(-9.5,-6.5) AD9(-8.5,-6.5) AD10(-7.5,-6.5) AD11(-6.5,-6.5) AD12(-5.5,-6.5) AD13(-4.5,-6.5) AD14(-3.5,-6.5) AD15(-2.5,-6.5) AD16(-1.5,-6.5) AD17(-0.5,-6.5) AD18(0.5,-6.5) AD19(1.5,-6.5) AD20(2.5,-6.5) AD21(3.5,-6.5) AD22(4.5,-6.5) AD23(5.5,-6.5) AD24(6.5,-6.5) AD25(7.5,-6.5) AD26(8.5,-6.5) AD27(9.5,-6.5) AD28(10.5,-6.5) AD29(11.5,-6.5) AD30(12.5,-6.5) AD31(13.5,-6.5) AD32(14.5,-6.5) AD33(15.5,-6.5) AD34(16.5,-6.5) AE1(-16.5,-7.5) AE2(-15.5,-7.5) AE3(-14.5,-7.5) AE4(-13.5,-7.5) AE5(-12.5,-7.5) AE6(-11.5,-7.5) AE7(-10.5,-7.5) AE8(-9.5,-7.5) AE9(-8.5,-7.5) AE10(-7.5,-7.5) AE11(-6.5,-7.5) AE12(-5.5,-7.5) AE13(-4.5,-7.5) AE14(-3.5,-7.5) AE15(-2.5,-7.5) AE16(-1.5,-7.5) AE17(-0.5,-7.5) AE18(0.5,-7.5) AE19(1.5,-7.5) AE20(2.5,-7.5) AE21(3.5,-7.5) AE22(4.5,-7.5) AE23(5.5,-7.5) AE24(6.5,-7.5) AE25(7.5,-7.5) AE26(8.5,-7.5) AE27(9.5,-7.5) AE28(10.5,-7.5) AE29(11.5,-7.5) AE30(12.5,-7.5) AE31(13.5,-7.5) AE32(14.5,-7.5) AE33(15.5,-7.5) AE34(16.5,-7.5) AF1(-16.5,-8.5) AF2(-15.5,-8.5) AF3(-14.5,-8.5) AF4(-13.5,-8.5) AF5(-12.5,-8.5) AF6(-11.5,-8.5) AF7(-10.5,-8.5) AF8(-9.5,-8.5) AF9(-8.5,-8.5) AF10(-7.5,-8.5) AF11(-6.5,-8.5) AF12(-5.5,-8.5) AF13(-4.5,-8.5) AF14(-3.5,-8.5) AF15(-2.5,-8.5) AF16(-1.5,-8.5) AF17(-0.5,-8.5) AF18(0.5,-8.5) AF19(1.5,-8.5) AF20(2.5,-8.5) AF21(3.5,-8.5) AF22(4.5,-8.5) AF23(5.5,-8.5) AF24(6.5,-8.5) AF25(7.5,-8.5) AF26(8.5,-8.5) AF27(9.5,-8.5) AF28(10.5,-8.5) AF29(11.5,-8.5) AF30(12.5,-8.5) AF31(13.5,-8.5) AF32(14.5,-8.5) AF33(15.5,-8.5) AF34(16.5,-8.5) AG1(-16.5,-9.5) AG2(-15.5,-9.5) AG3(-14.5,-9.5) AG4(-13.5,-9.5) AG5(-12.5,-9.5) AG6(-11.5,-9.5) AG7(-10.5,-9.5) AG8(-9.5,-9.5) AG9(-8.5,-9.5) AG10(-7.5,-9.5) AG11(-6.5,-9.5) AG12(-5.5,-9.5) AG13(-4.5,-9.5) AG14(-3.5,-9.5) AG15(-2.5,-9.5) AG16(-1.5,-9.5) AG17(-0.5,-9.5) AG18(0.5,-9.5) AG19(1.5,-9.5) AG20(2.5,-9.5) AG21(3.5,-9.5) AG22(4.5,-9.5) AG23(5.5,-9.5) AG24(6.5,-9.5) AG25(7.5,-9.5) AG26(8.5,-9.5) AG27(9.5,-9.5) AG28(10.5,-9.5) AG29(11.5,-9.5) AG30(12.5,-9.5) AG31(13.5,-9.5) AG32(14.5,-9.5) AG33(15.5,-9.5) AG34(16.5,-9.5) AH1(-16.5,-10.5) AH2(-15.5,-10.5) AH3(-14.5,-10.5) AH4(-13.5,-10.5) AH5(-12.5,-10.5) AH6(-11.5,-10.5) AH7(-10.5,-10.5) AH8(-9.5,-10.5) AH9(-8.5,-10.5) AH10(-7.5,-10.5) AH11(-6.5,-10.5) AH12(-5.5,-10.5) AH13(-4.5,-10.5) AH14(-3.5,-10.5) AH15(-2.5,-10.5) AH16(-1.5,-10.5) AH17(-0.5,-10.5) AH18(0.5,-10.5) AH19(1.5,-10.5) AH20(2.5,-10.5) AH21(3.5,-10.5) AH22(4.5,-10.5) AH23(5.5,-10.5) AH24(6.5,-10.5) AH25(7.5,-10.5) AH26(8.5,-10.5) AH27(9.5,-10.5) AH28(10.5,-10.5) AH29(11.5,-10.5) AH30(12.5,-10.5) AH31(13.5,-10.5) AH32(14.5,-10.5) AH33(15.5,-10.5) AH34(16.5,-10.5) AJ1(-16.5,-11.5) AJ2(-15.5,-11.5) AJ3(-14.5,-11.5) AJ4(-13.5,-11.5) AJ5(-12.5,-11.5) AJ6(-11.5,-11.5) AJ7(-10.5,-11.5) AJ8(-9.5,-11.5) AJ9(-8.5,-11.5) AJ10(-7.5,-11.5) AJ11(-6.5,-11.5) AJ12(-5.5,-11.5) AJ13(-4.5,-11.5) AJ14(-3.5,-11.5) AJ15(-2.5,-11.5) AJ16(-1.5,-11.5) AJ17(-0.5,-11.5) AJ18(0.5,-11.5) AJ19(1.5,-11.5) AJ20(2.5,-11.5) AJ21(3.5,-11.5) AJ22(4.5,-11.5) AJ23(5.5,-11.5) AJ24(6.5,-11.5) AJ25(7.5,-11.5) AJ26(8.5,-11.5) AJ27(9.5,-11.5) AJ28(10.5,-11.5) AJ29(11.5,-11.5) AJ30(12.5,-11.5) AJ31(13.5,-11.5) AJ32(14.5,-11.5) AJ33(15.5,-11.5) AJ34(16.5,-11.5) AK1(-16.5,-12.5) AK2(-15.5,-12.5) AK3(-14.5,-12.5) AK4(-13.5,-12.5) AK5(-12.5,-12.5) AK6(-11.5,-12.5) AK7(-10.5,-12.5) AK8(-9.5,-12.5) AK9(-8.5,-12.5) AK10(-7.5,-12.5) AK11(-6.5,-12.5) AK12(-5.5,-12.5) AK13(-4.5,-12.5) AK14(-3.5,-12.5) AK15(-2.5,-12.5) AK16(-1.5,-12.5) AK17(-0.5,-12.5) AK18(0.5,-12.5) AK19(1.5,-12.5) AK20(2.5,-12.5) AK21(3.5,-12.5) AK22(4.5,-12.5) AK23(5.5,-12.5) AK24(6.5,-12.5) AK25(7.5,-12.5) AK26(8.5,-12.5) AK27(9.5,-12.5) AK28(10.5,-12.5) AK29(11.5,-12.5) AK30(12.5,-12.5) AK31(13.5,-12.5) AK32(14.5,-12.5) AK33(15.5,-12.5) AK34(16.5,-12.5) AL1(-16.5,-13.5) AL2(-15.5,-13.5) AL3(-14.5,-13.5) AL4(-13.5,-13.5) AL5(-12.5,-13.5) AL6(-11.5,-13.5) AL7(-10.5,-13.5) AL8(-9.5,-13.5) AL9(-8.5,-13.5) AL10(-7.5,-13.5) AL11(-6.5,-13.5) AL12(-5.5,-13.5) AL13(-4.5,-13.5) AL14(-3.5,-13.5) AL15(-2.5,-13.5) AL16(-1.5,-13.5) AL17(-0.5,-13.5) AL18(0.5,-13.5) AL19(1.5,-13.5) AL20(2.5,-13.5) AL21(3.5,-13.5) AL22(4.5,-13.5) AL23(5.5,-13.5) AL24(6.5,-13.5) AL25(7.5,-13.5) AL26(8.5,-13.5) AL27(9.5,-13.5) AL28(10.5,-13.5) AL29(11.5,-13.5) AL30(12.5,-13.5) AL31(13.5,-13.5) AL32(14.5,-13.5) AL33(15.5,-13.5) AL34(16.5,-13.5) AM1(-16.5,-14.5) AM2(-15.5,-14.5) AM3(-14.5,-14.5) AM4(-13.5,-14.5) AM5(-12.5,-14.5) AM6(-11.5,-14.5) AM7(-10.5,-14.5) AM8(-9.5,-14.5) AM9(-8.5,-14.5) AM10(-7.5,-14.5) AM11(-6.5,-14.5) AM12(-5.5,-14.5) AM13(-4.5,-14.5) AM14(-3.5,-14.5) AM15(-2.5,-14.5) AM16(-1.5,-14.5) AM17(-0.5,-14.5) AM18(0.5,-14.5) AM19(1.5,-14.5) AM20(2.5,-14.5) AM21(3.5,-14.5) AM22(4.5,-14.5) AM23(5.5,-14.5) AM24(6.5,-14.5) AM25(7.5,-14.5) AM26(8.5,-14.5) AM27(9.5,-14.5) AM28(10.5,-14.5) AM29(11.5,-14.5) AM30(12.5,-14.5) AM31(13.5,-14.5) AM32(14.5,-14.5) AM33(15.5,-14.5) AM34(16.5,-14.5) AN1(-16.5,-15.5) AN2(-15.5,-15.5) AN3(-14.5,-15.5) AN4(-13.5,-15.5) AN5(-12.5,-15.5) AN6(-11.5,-15.5) AN7(-10.5,-15.5) AN8(-9.5,-15.5) AN9(-8.5,-15.5) AN10(-7.5,-15.5) AN11(-6.5,-15.5) AN12(-5.5,-15.5) AN13(-4.5,-15.5) AN14(-3.5,-15.5) AN15(-2.5,-15.5) AN16(-1.5,-15.5) AN17(-0.5,-15.5) AN18(0.5,-15.5) AN19(1.5,-15.5) AN20(2.5,-15.5) AN21(3.5,-15.5) AN22(4.5,-15.5) AN23(5.5,-15.5) AN24(6.5,-15.5) AN25(7.5,-15.5) AN26(8.5,-15.5) AN27(9.5,-15.5) AN28(10.5,-15.5) AN29(11.5,-15.5) AN30(12.5,-15.5) AN31(13.5,-15.5) AN32(14.5,-15.5) AN33(15.5,-15.5) AN34(16.5,-15.5) AP1(-16.5,-16.5) AP2(-15.5,-16.5) AP3(-14.5,-16.5) AP4(-13.5,-16.5) AP5(-12.5,-16.5) AP6(-11.5,-16.5) AP7(-10.5,-16.5) AP8(-9.5,-16.5) AP9(-8.5,-16.5) AP10(-7.5,-16.5) AP11(-6.5,-16.5) AP12(-5.5,-16.5) AP13(-4.5,-16.5) AP14(-3.5,-16.5) AP15(-2.5,-16.5) AP16(-1.5,-16.5) AP17(-0.5,-16.5) AP18(0.5,-16.5) AP19(1.5,-16.5) AP20(2.5,-16.5) AP21(3.5,-16.5) AP22(4.5,-16.5) AP23(5.5,-16.5) AP24(6.5,-16.5) AP25(7.5,-16.5) AP26(8.5,-16.5) AP27(9.5,-16.5) AP28(10.5,-16.5) AP29(11.5,-16.5) AP30(12.5,-16.5) AP31(13.5,-16.5) AP32(14.5,-16.5) AP33(15.5,-16.5) AP34(16.5,-16.5) B1(-16.5,15.5) B2(-15.5,15.5) B3(-14.5,15.5) B4(-13.5,15.5) B5(-12.5,15.5) B6(-11.5,15.5) B7(-10.5,15.5) B8(-9.5,15.5) B9(-8.5,15.5) B10(-7.5,15.5) B11(-6.5,15.5) B12(-5.5,15.5) B13(-4.5,15.5) B14(-3.5,15.5) B15(-2.5,15.5) B16(-1.5,15.5) B17(-0.5,15.5) B18(0.5,15.5) B19(1.5,15.5) B20(2.5,15.5) B21(3.5,15.5) B22(4.5,15.5) B23(5.5,15.5) B24(6.5,15.5) B25(7.5,15.5) B26(8.5,15.5) B27(9.5,15.5) B28(10.5,15.5) B29(11.5,15.5) B30(12.5,15.5) B31(13.5,15.5) B32(14.5,15.5) B33(15.5,15.5) B34(16.5,15.5) C1(-16.5,14.5) C2(-15.5,14.5) C3(-14.5,14.5) C4(-13.5,14.5) C5(-12.5,14.5) C6(-11.5,14.5) C7(-10.5,14.5) C8(-9.5,14.5) C9(-8.5,14.5) C10(-7.5,14.5) C11(-6.5,14.5) C12(-5.5,14.5) C13(-4.5,14.5) C14(-3.5,14.5) C15(-2.5,14.5) C16(-1.5,14.5) C17(-0.5,14.5) C18(0.5,14.5) C19(1.5,14.5) C20(2.5,14.5) C21(3.5,14.5) C22(4.5,14.5) C23(5.5,14.5) C24(6.5,14.5) C25(7.5,14.5) C26(8.5,14.5) C27(9.5,14.5) C28(10.5,14.5) C29(11.5,14.5) C30(12.5,14.5) C31(13.5,14.5) C32(14.5,14.5) C33(15.5,14.5) C34(16.5,14.5) D1(-16.5,13.5) D2(-15.5,13.5) D3(-14.5,13.5) D4(-13.5,13.5) D5(-12.5,13.5) D6(-11.5,13.5) D7(-10.5,13.5) D8(-9.5,13.5) D9(-8.5,13.5) D10(-7.5,13.5) D11(-6.5,13.5) D12(-5.5,13.5) D13(-4.5,13.5) D14(-3.5,13.5) D15(-2.5,13.5) D16(-1.5,13.5) D17(-0.5,13.5) D18(0.5,13.5) D19(1.5,13.5) D20(2.5,13.5) D21(3.5,13.5) D22(4.5,13.5) D23(5.5,13.5) D24(6.5,13.5) D25(7.5,13.5) D26(8.5,13.5) D27(9.5,13.5) D28(10.5,13.5) D29(11.5,13.5) D30(12.5,13.5) D31(13.5,13.5) D32(14.5,13.5) D33(15.5,13.5) D34(16.5,13.5) E1(-16.5,12.5) E2(-15.5,12.5) E3(-14.5,12.5) E4(-13.5,12.5) E5(-12.5,12.5) E6(-11.5,12.5) E7(-10.5,12.5) E8(-9.5,12.5) E9(-8.5,12.5) E10(-7.5,12.5) E11(-6.5,12.5) E12(-5.5,12.5) E13(-4.5,12.5) E14(-3.5,12.5) E15(-2.5,12.5) E16(-1.5,12.5) E17(-0.5,12.5) E18(0.5,12.5) E19(1.5,12.5) E20(2.5,12.5) E21(3.5,12.5) E22(4.5,12.5) E23(5.5,12.5) E24(6.5,12.5) E25(7.5,12.5) E26(8.5,12.5) E27(9.5,12.5) E28(10.5,12.5) E29(11.5,12.5) E30(12.5,12.5) E31(13.5,12.5) E32(14.5,12.5) E33(15.5,12.5) E34(16.5,12.5) F1(-16.5,11.5) F2(-15.5,11.5) F3(-14.5,11.5) F4(-13.5,11.5) F5(-12.5,11.5) F6(-11.5,11.5) F7(-10.5,11.5) F8(-9.5,11.5) F9(-8.5,11.5) F10(-7.5,11.5) F11(-6.5,11.5) F12(-5.5,11.5) F13(-4.5,11.5) F14(-3.5,11.5) F15(-2.5,11.5) F16(-1.5,11.5) F17(-0.5,11.5) F18(0.5,11.5) F19(1.5,11.5) F20(2.5,11.5) F21(3.5,11.5) F22(4.5,11.5) F23(5.5,11.5) F24(6.5,11.5) F25(7.5,11.5) F26(8.5,11.5) F27(9.5,11.5) F28(10.5,11.5) F29(11.5,11.5) F30(12.5,11.5) F31(13.5,11.5) F32(14.5,11.5) F33(15.5,11.5) F34(16.5,11.5) G1(-16.5,10.5) G2(-15.5,10.5) G3(-14.5,10.5) G4(-13.5,10.5) G5(-12.5,10.5) G6(-11.5,10.5) G7(-10.5,10.5) G8(-9.5,10.5) G9(-8.5,10.5) G10(-7.5,10.5) G11(-6.5,10.5) G12(-5.5,10.5) G13(-4.5,10.5) G14(-3.5,10.5) G15(-2.5,10.5) G16(-1.5,10.5) G17(-0.5,10.5) G18(0.5,10.5) G19(1.5,10.5) G20(2.5,10.5) G21(3.5,10.5) G22(4.5,10.5) G23(5.5,10.5) G24(6.5,10.5) G25(7.5,10.5) G26(8.5,10.5) G27(9.5,10.5) G28(10.5,10.5) G29(11.5,10.5) G30(12.5,10.5) G31(13.5,10.5) G32(14.5,10.5) G33(15.5,10.5) G34(16.5,10.5) H1(-16.5,9.5) H2(-15.5,9.5) H3(-14.5,9.5) H4(-13.5,9.5) H5(-12.5,9.5) H6(-11.5,9.5) H7(-10.5,9.5) H8(-9.5,9.5) H9(-8.5,9.5) H10(-7.5,9.5) H11(-6.5,9.5) H12(-5.5,9.5) H13(-4.5,9.5) H14(-3.5,9.5) H15(-2.5,9.5) H16(-1.5,9.5) H17(-0.5,9.5) H18(0.5,9.5) H19(1.5,9.5) H20(2.5,9.5) H21(3.5,9.5) H22(4.5,9.5) H23(5.5,9.5) H24(6.5,9.5) H25(7.5,9.5) H26(8.5,9.5) H27(9.5,9.5) H28(10.5,9.5) H29(11.5,9.5) H30(12.5,9.5) H31(13.5,9.5) H32(14.5,9.5) H33(15.5,9.5) H34(16.5,9.5) J1(-16.5,8.5) J2(-15.5,8.5) J3(-14.5,8.5) J4(-13.5,8.5) J5(-12.5,8.5) J6(-11.5,8.5) J7(-10.5,8.5) J8(-9.5,8.5) J9(-8.5,8.5) J10(-7.5,8.5) J11(-6.5,8.5) J12(-5.5,8.5) J13(-4.5,8.5) J14(-3.5,8.5) J15(-2.5,8.5) J16(-1.5,8.5) J17(-0.5,8.5) J18(0.5,8.5) J19(1.5,8.5) J20(2.5,8.5) J21(3.5,8.5) J22(4.5,8.5) J23(5.5,8.5) J24(6.5,8.5) J25(7.5,8.5) J26(8.5,8.5) J27(9.5,8.5) J28(10.5,8.5) J29(11.5,8.5) J30(12.5,8.5) J31(13.5,8.5) J32(14.5,8.5) J33(15.5,8.5) J34(16.5,8.5) K1(-16.5,7.5) K2(-15.5,7.5) K3(-14.5,7.5) K4(-13.5,7.5) K5(-12.5,7.5) K6(-11.5,7.5) K7(-10.5,7.5) K8(-9.5,7.5) K9(-8.5,7.5) K10(-7.5,7.5) K11(-6.5,7.5) K12(-5.5,7.5) K13(-4.5,7.5) K14(-3.5,7.5) K15(-2.5,7.5) K16(-1.5,7.5) K17(-0.5,7.5) K18(0.5,7.5) K19(1.5,7.5) K20(2.5,7.5) K21(3.5,7.5) K22(4.5,7.5) K23(5.5,7.5) K24(6.5,7.5) K25(7.5,7.5) K26(8.5,7.5) K27(9.5,7.5) K28(10.5,7.5) K29(11.5,7.5) K30(12.5,7.5) K31(13.5,7.5) K32(14.5,7.5) K33(15.5,7.5) K34(16.5,7.5) L1(-16.5,6.5) L2(-15.5,6.5) L3(-14.5,6.5) L4(-13.5,6.5) L5(-12.5,6.5) L6(-11.5,6.5) L7(-10.5,6.5) L8(-9.5,6.5) L9(-8.5,6.5) L10(-7.5,6.5) L11(-6.5,6.5) L12(-5.5,6.5) L13(-4.5,6.5) L14(-3.5,6.5) L15(-2.5,6.5) L16(-1.5,6.5) L17(-0.5,6.5) L18(0.5,6.5) L19(1.5,6.5) L20(2.5,6.5) L21(3.5,6.5) L22(4.5,6.5) L23(5.5,6.5) L24(6.5,6.5) L25(7.5,6.5) L26(8.5,6.5) L27(9.5,6.5) L28(10.5,6.5) L29(11.5,6.5) L30(12.5,6.5) L31(13.5,6.5) L32(14.5,6.5) L33(15.5,6.5) L34(16.5,6.5) M1(-16.5,5.5) M2(-15.5,5.5) M3(-14.5,5.5) M4(-13.5,5.5) M5(-12.5,5.5) M6(-11.5,5.5) M7(-10.5,5.5) M8(-9.5,5.5) M9(-8.5,5.5) M10(-7.5,5.5) M11(-6.5,5.5) M12(-5.5,5.5) M13(-4.5,5.5) M14(-3.5,5.5) M15(-2.5,5.5) M16(-1.5,5.5) M17(-0.5,5.5) M18(0.5,5.5) M19(1.5,5.5) M20(2.5,5.5) M21(3.5,5.5) M22(4.5,5.5) M23(5.5,5.5) M24(6.5,5.5) M25(7.5,5.5) M26(8.5,5.5) M27(9.5,5.5) M28(10.5,5.5) M29(11.5,5.5) M30(12.5,5.5) M31(13.5,5.5) M32(14.5,5.5) M33(15.5,5.5) M34(16.5,5.5) N1(-16.5,4.5) N2(-15.5,4.5) N3(-14.5,4.5) N4(-13.5,4.5) N5(-12.5,4.5) N6(-11.5,4.5) N7(-10.5,4.5) N8(-9.5,4.5) N9(-8.5,4.5) N10(-7.5,4.5) N11(-6.5,4.5) N12(-5.5,4.5) N13(-4.5,4.5) N14(-3.5,4.5) N15(-2.5,4.5) N16(-1.5,4.5) N17(-0.5,4.5) N18(0.5,4.5) N19(1.5,4.5) N20(2.5,4.5) N21(3.5,4.5) N22(4.5,4.5) N23(5.5,4.5) N24(6.5,4.5) N25(7.5,4.5) N26(8.5,4.5) N27(9.5,4.5) N28(10.5,4.5) N29(11.5,4.5) N30(12.5,4.5) N31(13.5,4.5) N32(14.5,4.5) N33(15.5,4.5) N34(16.5,4.5) P1(-16.5,3.5) P2(-15.5,3.5) P3(-14.5,3.5) P4(-13.5,3.5) P5(-12.5,3.5) P6(-11.5,3.5) P7(-10.5,3.5) P8(-9.5,3.5) P9(-8.5,3.5) P10(-7.5,3.5) P11(-6.5,3.5) P12(-5.5,3.5) P13(-4.5,3.5) P14(-3.5,3.5) P15(-2.5,3.5) P16(-1.5,3.5) P17(-0.5,3.5) P18(0.5,3.5) P19(1.5,3.5) P20(2.5,3.5) P21(3.5,3.5) P22(4.5,3.5) P23(5.5,3.5) P24(6.5,3.5) P25(7.5,3.5) P26(8.5,3.5) P27(9.5,3.5) P28(10.5,3.5) P29(11.5,3.5) P30(12.5,3.5) P31(13.5,3.5) P32(14.5,3.5) P33(15.5,3.5) P34(16.5,3.5) R1(-16.5,2.5) R2(-15.5,2.5) R3(-14.5,2.5) R4(-13.5,2.5) R5(-12.5,2.5) R6(-11.5,2.5) R7(-10.5,2.5) R8(-9.5,2.5) R9(-8.5,2.5) R10(-7.5,2.5) R11(-6.5,2.5) R12(-5.5,2.5) R13(-4.5,2.5) R14(-3.5,2.5) R15(-2.5,2.5) R16(-1.5,2.5) R17(-0.5,2.5) R18(0.5,2.5) R19(1.5,2.5) R20(2.5,2.5) R21(3.5,2.5) R22(4.5,2.5) R23(5.5,2.5) R24(6.5,2.5) R25(7.5,2.5) R26(8.5,2.5) R27(9.5,2.5) R28(10.5,2.5) R29(11.5,2.5) R30(12.5,2.5) R31(13.5,2.5) R32(14.5,2.5) R33(15.5,2.5) R34(16.5,2.5) T1(-16.5,1.5) T2(-15.5,1.5) T3(-14.5,1.5) T4(-13.5,1.5) T5(-12.5,1.5) T6(-11.5,1.5) T7(-10.5,1.5) T8(-9.5,1.5) T9(-8.5,1.5) T10(-7.5,1.5) T11(-6.5,1.5) T12(-5.5,1.5) T13(-4.5,1.5) T14(-3.5,1.5) T15(-2.5,1.5) T16(-1.5,1.5) T17(-0.5,1.5) T18(0.5,1.5) T19(1.5,1.5) T20(2.5,1.5) T21(3.5,1.5) T22(4.5,1.5) T23(5.5,1.5) T24(6.5,1.5) T25(7.5,1.5) T26(8.5,1.5) T27(9.5,1.5) T28(10.5,1.5) T29(11.5,1.5) T30(12.5,1.5) T31(13.5,1.5) T32(14.5,1.5) T33(15.5,1.5) T34(16.5,1.5) U1(-16.5,0.5) U2(-15.5,0.5) U3(-14.5,0.5) U4(-13.5,0.5) U5(-12.5,0.5) U6(-11.5,0.5) U7(-10.5,0.5) U8(-9.5,0.5) U9(-8.5,0.5) U10(-7.5,0.5) U11(-6.5,0.5) U12(-5.5,0.5) U13(-4.5,0.5) U14(-3.5,0.5) U15(-2.5,0.5) U16(-1.5,0.5) U17(-0.5,0.5) U18(0.5,0.5) U19(1.5,0.5) U20(2.5,0.5) U21(3.5,0.5) U22(4.5,0.5) U23(5.5,0.5) U24(6.5,0.5) U25(7.5,0.5) U26(8.5,0.5) U27(9.5,0.5) U28(10.5,0.5) U29(11.5,0.5) U30(12.5,0.5) U31(13.5,0.5) U32(14.5,0.5) U33(15.5,0.5) U34(16.5,0.5) V1(-16.5,-0.5) V2(-15.5,-0.5) V3(-14.5,-0.5) V4(-13.5,-0.5) V5(-12.5,-0.5) V6(-11.5,-0.5) V7(-10.5,-0.5) V8(-9.5,-0.5) V9(-8.5,-0.5) V10(-7.5,-0.5) V11(-6.5,-0.5) V12(-5.5,-0.5) V13(-4.5,-0.5) V14(-3.5,-0.5) V15(-2.5,-0.5) V16(-1.5,-0.5) V17(-0.5,-0.5) V18(0.5,-0.5) V19(1.5,-0.5) V20(2.5,-0.5) V21(3.5,-0.5) V22(4.5,-0.5) V23(5.5,-0.5) V24(6.5,-0.5) V25(7.5,-0.5) V26(8.5,-0.5) V27(9.5,-0.5) V28(10.5,-0.5) V29(11.5,-0.5) V30(12.5,-0.5) V31(13.5,-0.5) V32(14.5,-0.5) V33(15.5,-0.5) V34(16.5,-0.5) W1(-16.5,-1.5) W2(-15.5,-1.5) W3(-14.5,-1.5) W4(-13.5,-1.5) W5(-12.5,-1.5) W6(-11.5,-1.5) W7(-10.5,-1.5) W8(-9.5,-1.5) W9(-8.5,-1.5) W10(-7.5,-1.5) W11(-6.5,-1.5) W12(-5.5,-1.5) W13(-4.5,-1.5) W14(-3.5,-1.5) W15(-2.5,-1.5) W16(-1.5,-1.5) W17(-0.5,-1.5) W18(0.5,-1.5) W19(1.5,-1.5) W20(2.5,-1.5) W21(3.5,-1.5) W22(4.5,-1.5) W23(5.5,-1.5) W24(6.5,-1.5) W25(7.5,-1.5) W26(8.5,-1.5) W27(9.5,-1.5) W28(10.5,-1.5) W29(11.5,-1.5) W30(12.5,-1.5) W31(13.5,-1.5) W32(14.5,-1.5) W33(15.5,-1.5) W34(16.5,-1.5) Y1(-16.5,-2.5) Y2(-15.5,-2.5) Y3(-14.5,-2.5) Y4(-13.5,-2.5) Y5(-12.5,-2.5) Y6(-11.5,-2.5) Y7(-10.5,-2.5) Y8(-9.5,-2.5) Y9(-8.5,-2.5) Y10(-7.5,-2.5) Y11(-6.5,-2.5) Y12(-5.5,-2.5) Y13(-4.5,-2.5) Y14(-3.5,-2.5) Y15(-2.5,-2.5) Y16(-1.5,-2.5) Y17(-0.5,-2.5) Y18(0.5,-2.5) Y19(1.5,-2.5) Y20(2.5,-2.5) Y21(3.5,-2.5) Y22(4.5,-2.5) Y23(5.5,-2.5) Y24(6.5,-2.5) Y25(7.5,-2.5) Y26(8.5,-2.5) Y27(9.5,-2.5) Y28(10.5,-2.5) Y29(11.5,-2.5) Y30(12.5,-2.5) Y31(13.5,-2.5) Y32(14.5,-2.5) Y33(15.5,-2.5) Y34(16.5,-2.5)
LPTM21L-CAG100
  round 0.368 smd: A1(-3.6,3.6) A2(-2.8,3.6) A3(-2,3.6) A4(-1.2,3.6) A5(-0.4,3.6) A6(0.4,3.6) A7(1.2,3.6) A8(2,3.6) A9(2.8,3.6) A10(3.6,3.6) B1(-3.6,2.8) B2(-2.8,2.8) B3(-2,2.8) B4(-1.2,2.8) B5(-0.4,2.8) B6(0.4,2.8) B7(1.2,2.8) B8(2,2.8) B9(2.8,2.8) B10(3.6,2.8) C1(-3.6,2) C2(-2.8,2) C3(-2,2) C4(-1.2,2) C5(-0.4,2) C6(0.4,2) C7(1.2,2) C8(2,2) C9(2.8,2) C10(3.6,2) D1(-3.6,1.2) D2(-2.8,1.2) D3(-2,1.2) D4(-1.2,1.2) D5(-0.4,1.2) D6(0.4,1.2) D7(1.2,1.2) D8(2,1.2) D9(2.8,1.2) D10(3.6,1.2) E1(-3.6,0.4) E2(-2.8,0.4) E3(-2,0.4) E4(-1.2,0.4) E5(-0.4,0.4) E6(0.4,0.4) E7(1.2,0.4) E8(2,0.4) E9(2.8,0.4) E10(3.6,0.4) F1(-3.6,-0.4) F2(-2.8,-0.4) F3(-2,-0.4) F4(-1.2,-0.4) F5(-0.4,-0.4) F6(0.4,-0.4) F7(1.2,-0.4) F8(2,-0.4) F9(2.8,-0.4) F10(3.6,-0.4) G1(-3.6,-1.2) G2(-2.8,-1.2) G3(-2,-1.2) G4(-1.2,-1.2) G5(-0.4,-1.2) G6(0.4,-1.2) G7(1.2,-1.2) G8(2,-1.2) G9(2.8,-1.2) G10(3.6,-1.2) H1(-3.6,-2) H2(-2.8,-2) H3(-2,-2) H4(-1.2,-2) H5(-0.4,-2) H6(0.4,-2) H7(1.2,-2) H8(2,-2) H9(2.8,-2) H10(3.6,-2) J1(-3.6,-2.8) J2(-2.8,-2.8) J3(-2,-2.8) J4(-1.2,-2.8) J5(-0.4,-2.8) J6(0.4,-2.8) J7(1.2,-2.8) J8(2,-2.8) J9(2.8,-2.8) J10(3.6,-2.8) K1(-3.6,-3.6) K2(-2.8,-3.6) K3(-2,-3.6) K4(-1.2,-3.6) K5(-0.4,-3.6) K6(0.4,-3.6) K7(1.2,-3.6) K8(2,-3.6) K9(2.8,-3.6) K10(3.6,-3.6)
MMBT2222ALT-1
  rect 1x1.4 smd: B(-0.95,-1.1) C(0,1.1) E(0.95,-1.1)
PPPC062LJBN-RC
  rect 1.524x1.524 hole 1.016: 1(-6.35,-12.84)
  round 1.524 hole 1.016: 2(-3.81,-12.84) 3(-1.27,-12.84) 4(1.27,-12.84) 5(3.81,-12.84) 6(6.35,-12.84) 7(-6.35,-10.3) 8(-3.81,-10.3) 9(-1.27,-10.3) 10(1.27,-10.3) 11(3.81,-10.3) 12(6.35,-10.3)
QFN6-MP2013
  rect 0.7x0.25 smd: 1(-0.95,0.65) 2(-0.95,0) 3(-0.95,-0.65) 4(0.95,-0.65) 5(0.95,0) 6(0.95,0.65)
  rect 0.7x1.4 smd: 7(0,0)
QFN24N4X4P0_5
  oval 0.25x0.8 smd: 1(-1.25,-1.95) 2(-0.75,-1.95) 3(-0.25,-1.95) 4(0.25,-1.95) 5(0.75,-1.95) 6(1.25,-1.95) 13(1.25,1.95) 14(0.75,1.95) 15(0.25,1.95) 16(-0.25,1.95) 17(-0.75,1.95) 18(-1.25,1.95)
  oval 0.8x0.25 smd: 7(1.95,-1.249) 8(1.95,-0.75) 9(1.95,-0.25) 10(1.95,0.25) 11(1.95,0.75) 12(1.95,1.25) 19(-1.95,1.25) 20(-1.95,0.75) 21(-1.95,0.25) 22(-1.95,-0.25) 23(-1.95,-0.75) 24(-1.95,-1.249)
  rect 2.5x2.5 smd: 25(0,0)
QFN-23
  custom 0.225x0.225 smd: 1(-1.85,2.15) 2(-1.85,2.15) 17(1.85,2.15) 18(1.85,2.15)
  rect 0.9x0.3 smd: 3(-1.85,1.1) 4(-1.85,0.4) 6(-1.85,-1) 13(1.85,-1) 15(1.85,0.4) 16(1.85,1.1)
  rect 1.2x0.3 smd: 5(-1.7,-0.3) 14(1.7,-0.3)
  custom 0.3x0.3 smd: 7(-1.7,-2.15) 8(-1.7,-2.15) 11(1.7,-2.15) 12(1.7,-2.15)
  custom 0.187x0.187 smd: 9(0,-1.65) 10(0,-1.65)
  rect 0.25x1.05 smd: 19(1,2.275) 20(0.5,2.275) 21(0,2.275) 22(-0.5,2.275) 23(-1,2.275)
R0201
  rect 0.275x0.3 smd: 1(-0.262,0) 2(0.262,0)
R0402
  rect 0.65x0.65 smd: 1(-0.501,0) 2(0.501,0)
R0603
  rect 0.813x0.762 smd: 1(-0.762,0) 2(0.762,0)
R3637
  rect 2.95x1.68 smd: 1(-3.735,4.115) 2(3.735,4.115)
  rect 2.95x7.62 smd: 3(-3.735,-1.145) 4(3.735,-1.145)
RAD_CAN_A768MS
  rect 4.4x2.2 smd: 1(4.45,0) 2(-4.45,0)
RES0402
  rect 0.56x0.63 smd: 1(-0.485,0) 2(0.485,0)
SC-88
  rect 0.4x1 smd: 1(-0.65,-1.1) 2(0,-1.1) 3(0.65,-1.1) 4(0.65,1.1) 5(0,1.1) 6(-0.65,1.1)
SMD
  rect 1.6x2.5 smd: 1(-2.2,0) 2(2.2,0)
SMD6_AX3HAF1
  rect 0.9x1.1 smd: 1(-1.2,-0.8) 2(0,-0.8) 3(1.2,-0.8) 4(1.2,0.8) 5(0,0.8) 6(-1.2,0.8)
SO8_50_244
  rect 1.55x0.6 smd: 1(-2.7,1.905) 2(-2.7,0.635) 3(-2.7,-0.635) 4(-2.7,-1.905) 5(2.7,-1.905) 6(2.7,-0.635) 7(2.7,0.635) 8(2.7,1.905)
SOT23-3
  rect 0.8x0.9 smd: B(-0.95,-1) C(0,1) E(0.95,-1)
SOT23_MGSF1N02L
  rect 0.56x0.95 smd: D(0,0.975) G(-0.95,-0.975) S(0.95,-0.975)
SOT89-5
  rect 0.711x1.524 smd: 1(-1.5,-1.85) 3(1.5,-1.85) 4(1.5,1.85) 5(-1.5,1.85)
  custom 0.5x0.5 smd: 2(0,0)
SOT-563-6
  oval 0.3x0.7 smd: 1(-0.5,-0.74) 2(0,-0.74) 3(0.5,-0.74) 4(0.5,0.74) 5(0,0.74) 6(-0.5,0.74)
SPM6530T-2R2M
  rect 1.85x3.4 smd: 1(-2.775,0) 2(2.775,0)
SRP4020TA-1R5M
  rect 1.5x2.4 smd: 1(-1.85,0) 2(1.85,0)
SRP4020TA-2R2M
  rect 1.5x2.4 smd: 1(-1.85,0) 2(1.85,0)
SRP4020TA-3R3M
  rect 1.5x2.4 smd: 1(-1.85,0) 2(1.85,0)
TC7343
  rect 2.6x3 smd: 1(-3.2,0) 2(3.2,0)
TDA08H0SB1
  rect 1.27x0.76 smd: 1(-3.81,4.445) 2(-3.81,3.175) 3(-3.81,1.905) 4(-3.81,0.635) 5(-3.81,-0.635) 6(-3.81,-1.905) 7(-3.81,-3.175) 8(-3.81,-4.445) 9(3.81,-4.445) 10(3.81,-3.175) 11(3.81,-1.905) 12(3.81,-0.635) 13(3.81,0.635) 14(3.81,1.905) 15(3.81,3.175) 16(3.81,4.445)
TO-277A
  rect 1.4x1.27 smd: A1(1.041,-2.772) A2(-1.041,-2.772)
  rect 4.8x4.72 smd: K(0,1.038)
